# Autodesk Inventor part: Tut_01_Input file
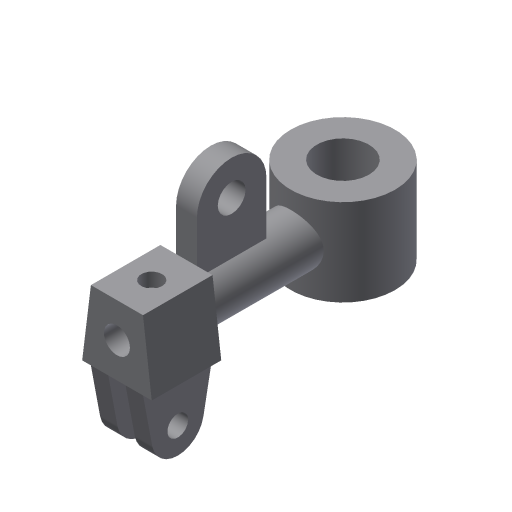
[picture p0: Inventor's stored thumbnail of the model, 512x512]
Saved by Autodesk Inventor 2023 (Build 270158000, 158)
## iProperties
Shininess: 77.0
Length Units: 11269
Angle Units: 11279
Time Units: 11290
Mass Units: 11283
Length Display Precision: 3
Angle Display Precision: 2
Created: 2001-12
Part Number: Tut_01_Input file
Document SubType Name: Modeling
Density: 1 g/cm^3
Material: Generic
Appearance: Default
Density: 0.0
Volumn: 0.0
Area: 0.0
PropertySet Name: Model Information
Control State: 0
Master: False
Checked Out: False
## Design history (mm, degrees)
sketch "Sketch1"
  geometry: C1 r 30 at (0, 0); 1 further point
  constraints: 1 centre point, 1 coincident, 1 other
  dimensions: "d0" = 60 diameter of C1
extrude "Extrusion1" new body sketch "Sketch1" stored distance "d1" = 50; taper "d2" = 0 deg
sketch "Sketch2"
  geometry: C1 r 15 at (0, 0); 1 further point
  constraints: 1 centre point, 1 coincident, 1 other
  dimensions: "d3" = 30 diameter of C1
extrude "Extrusion2" join sketch "Sketch2" distance "d4" = 130; taper "d5" = 0 deg
sketch "Sketch3"
  geometry: L1 (-15, 20)-(-20, -20); L2 (-20, -20)-(20, -20); L3 (20, -20)-(15, 20); L4 (15, 20)-(-15, 20); C1 r 15 at (0, 0) reference
  constraints: 8 end point, 1 equal length, 1 horizontal, 1 parallel
  dimensions: "d6" = 40 distance of L1.end L2.end; "d7" = 30 distance of L3.end L1.start; "d8" = 20 distance from line of C1.centre L4; "d9" = 40 distance between parallel lines of L4 L2; "d10" = 20 horizontal distance of C1.centre L2.end
extrude "Extrusion3" join sketch "Sketch3" distance "d11" = 40; taper "d12" = 0 deg
sketch "Sketch4"
  geometry: L1 (-90, 44)-(-90, 10.92); L2 (-90, 10.92)-(-50, 10.92); L3 (-50, 10.92)-(-50, 44); L4 (-90, 20)-(-90, -20) reference; L5 (-130, 20)-(-90, 20) reference; L6 (-90, -20)-(-90, 20) reference; C1 r 8 at (-70, 44); A1 r 20 centre (-70, 44) between (-50, 44) and (-90, 44); 1 further point
  constraints: 6 end point, 2 centre point, 2 point on circle, 2 tangent, 1 coincident, 1 midpoint, 1 parallel, 1 perpendicular, 1 point on line, 1 vertical
  dimensions: "d13" = 40 distance of L1.end L2.end; "d15" = 24 distance from line of L5 A1.centre; "d16" = 16 diameter of C1
extrude "Extrusion4" join sketch "Sketch4" stored distance "d17" = 12; taper "d18" = 0 deg
sketch "Sketch5"
  geometry: L1 (-130, -20)-(-124.738, -47.791); L2 (-95.262, -47.791)-(-90, -20); L3 (-90, -20)-(-130, -20); L4 (-130, -20)-(-90, -20) reference; L5 (-90, 20)-(-90, -20) reference; L6 (-130, 20)-(-130, -20) reference; L7 (-65.219, 30.926)-(-65.219, -115.614); L8 (-110, 38.032)-(-110, -78.704); C1 r 6 at (-110, -45); A1 r 15 centre (-110, -45) between (-124.738, -47.791) and (-95.262, -47.791)
  constraints: 10 end point, 3 point on line, 2 centre point, 2 collinear, 2 point on circle, 2 tangent, 2 vertical, 1 coincident, 1 horizontal
  dimensions: "d19" = 15 radius of A1; "d20" = 25 distance from line of L3 A1.centre; "d27" = 12 diameter of C1; "d53" = 20 distance between parallel lines of L6 L8
extrude "Extrusion5" join sketch "Sketch5" stored distance "d21" = 30; taper "d22" = 0 deg
sketch "Sketch6"
  geometry: L1 (-5, -20)-(5, -20); L2 (5, -20)-(5, -78.834); L3 (5, -78.834)-(-5, -78.834); L4 (-5, -78.834)-(-5, -20); L5 (-15, -20)-(15, -20) reference; L6 (15, -47.791)-(15, -20) reference
  constraints: 8 end point, 2 parallel, 1 collinear, 1 horizontal, 1 perpendicular
  dimensions: "d23" = 10 distance of L2.end L3.end; "d24" = 10 distance between parallel lines of L6 L2
extrude "Extrusion6" cut sketch "Sketch6" distance "d25" = 40; taper "d26" = 0 deg
sketch "Sketch7"
  geometry: 1 further point
hole "Hole1" sketch "Sketch7" at (0, 0) diameter "d28" = 15; stored, may be unused: countersink angle "d32" = 82 deg, drill point angle "d34" = 0 deg; dims "d29" = 6, "d30" = 4, "d31" = 2, "d33" = 110
sketch "Sketch8"
  geometry: L1 (30, 0)-(0, 0) reference; L2 (30, 0)-(30, 40) reference; 1 further point
  dimensions: "d35" = 20 distance from line of L1 point (15, 20); "d36" = 15 distance from line of L2 point (15, 20)
hole "Hole2" sketch "Sketch8" at (15, 20) diameter "d37" = 12; stored, may be unused: countersink angle "d41" = 82 deg, drill point angle "d43" = 0 deg; dims "d38" = 6, "d39" = 4, "d40" = 2, "d42" = 8
sketch "Sketch9"
  geometry: C1 r 30 at (0, 0) reference
hole "Hole3" sketch "Sketch9" at (0, 0) diameter "d44" = 30; stored, may be unused: countersink angle "d48" = 82 deg, drill point angle "d50" = 0 deg; dims "d45" = 6, "d46" = 4, "d47" = 2, "d49" = 8
body "Solid1"
